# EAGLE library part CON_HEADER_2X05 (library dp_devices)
2x05 pin header
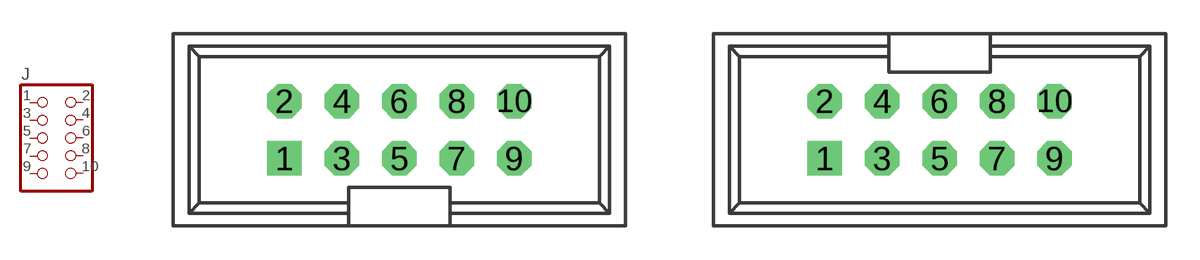
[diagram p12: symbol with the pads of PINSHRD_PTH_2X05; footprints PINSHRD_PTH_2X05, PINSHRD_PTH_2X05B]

Designator prefix J

## CON_HEADER_2X05-PTH+SHROUDED_A  [PINSHRD_PTH_2X05]
1  1  pas
2  2  pas
3  3  pas
4  4  pas
5  5  pas
6  6  pas
7  7  pas
8  8  pas
9  9  pas
10  10  pas

## CON_HEADER_2X05-PTH+SHROUDED_B  [PINSHRD_PTH_2X05B]
Pads as for PINSHRD_PTH_2X05

## CON_HEADER_2X05-SMD+SHROUDED  [PINSHRD_SMT_2X05]
Pads as for PINSHRD_PTH_2X05

## CON_HEADER_2X05-PTH  [M2X5]
Pads as for PINSHRD_PTH_2X05

## Footprint PINSHRD_PTH_2X05 (pad centres in mm)
drill 1.016 square: 1 -5.08,-1.27
drill 1.016 octagon: 2 -5.08,1.27; 3 -2.54,-1.27; 4 -2.54,1.27; 5 0,-1.27; 6 0,1.27; 7 2.54,-1.27; 8 2.54,1.27; 9 5.08,-1.27; 10 5.08,1.27

## Footprint PINSHRD_PTH_2X05B (pad centres in mm)
2X5 Pin header with flipped shrouded case
drill 1.016 square: 1 -5.08,-1.27
drill 1.016 octagon: 2 -5.08,1.27; 3 -2.54,-1.27; 4 -2.54,1.27; 5 0,-1.27; 6 0,1.27; 7 2.54,-1.27; 8 2.54,1.27; 9 5.08,-1.27; 10 5.08,1.27

## Footprint PINSHRD_SMT_2X05 (pad centres in mm)
pitch = 0.100 [2.54], 2x5 source: http://www.mlelectronic.com/shrouded-headers/shrouded-headers-100.asp
smd 1.02 x 3.75: 1 -5.08,-3.107; 2 -5.08,3.107; 3 -2.54,-3.107; 4 -2.54,3.107; 5 0,-3.107; 6 0,3.107; 7 2.54,-3.107; 8 2.54,3.107; 9 5.08,-3.107; 10 5.08,3.107

## Footprint M2X5 (pad centres in mm)
drill 0.8 square: 1 -5.08,-1.27
drill 0.8 round: 2 -5.08,1.27; 3 -2.54,-1.27; 4 -2.54,1.27; 5 0,-1.27; 6 0,1.27; 7 2.54,-1.27; 8 2.54,1.27; 9 5.08,-1.27; 10 5.08,1.27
